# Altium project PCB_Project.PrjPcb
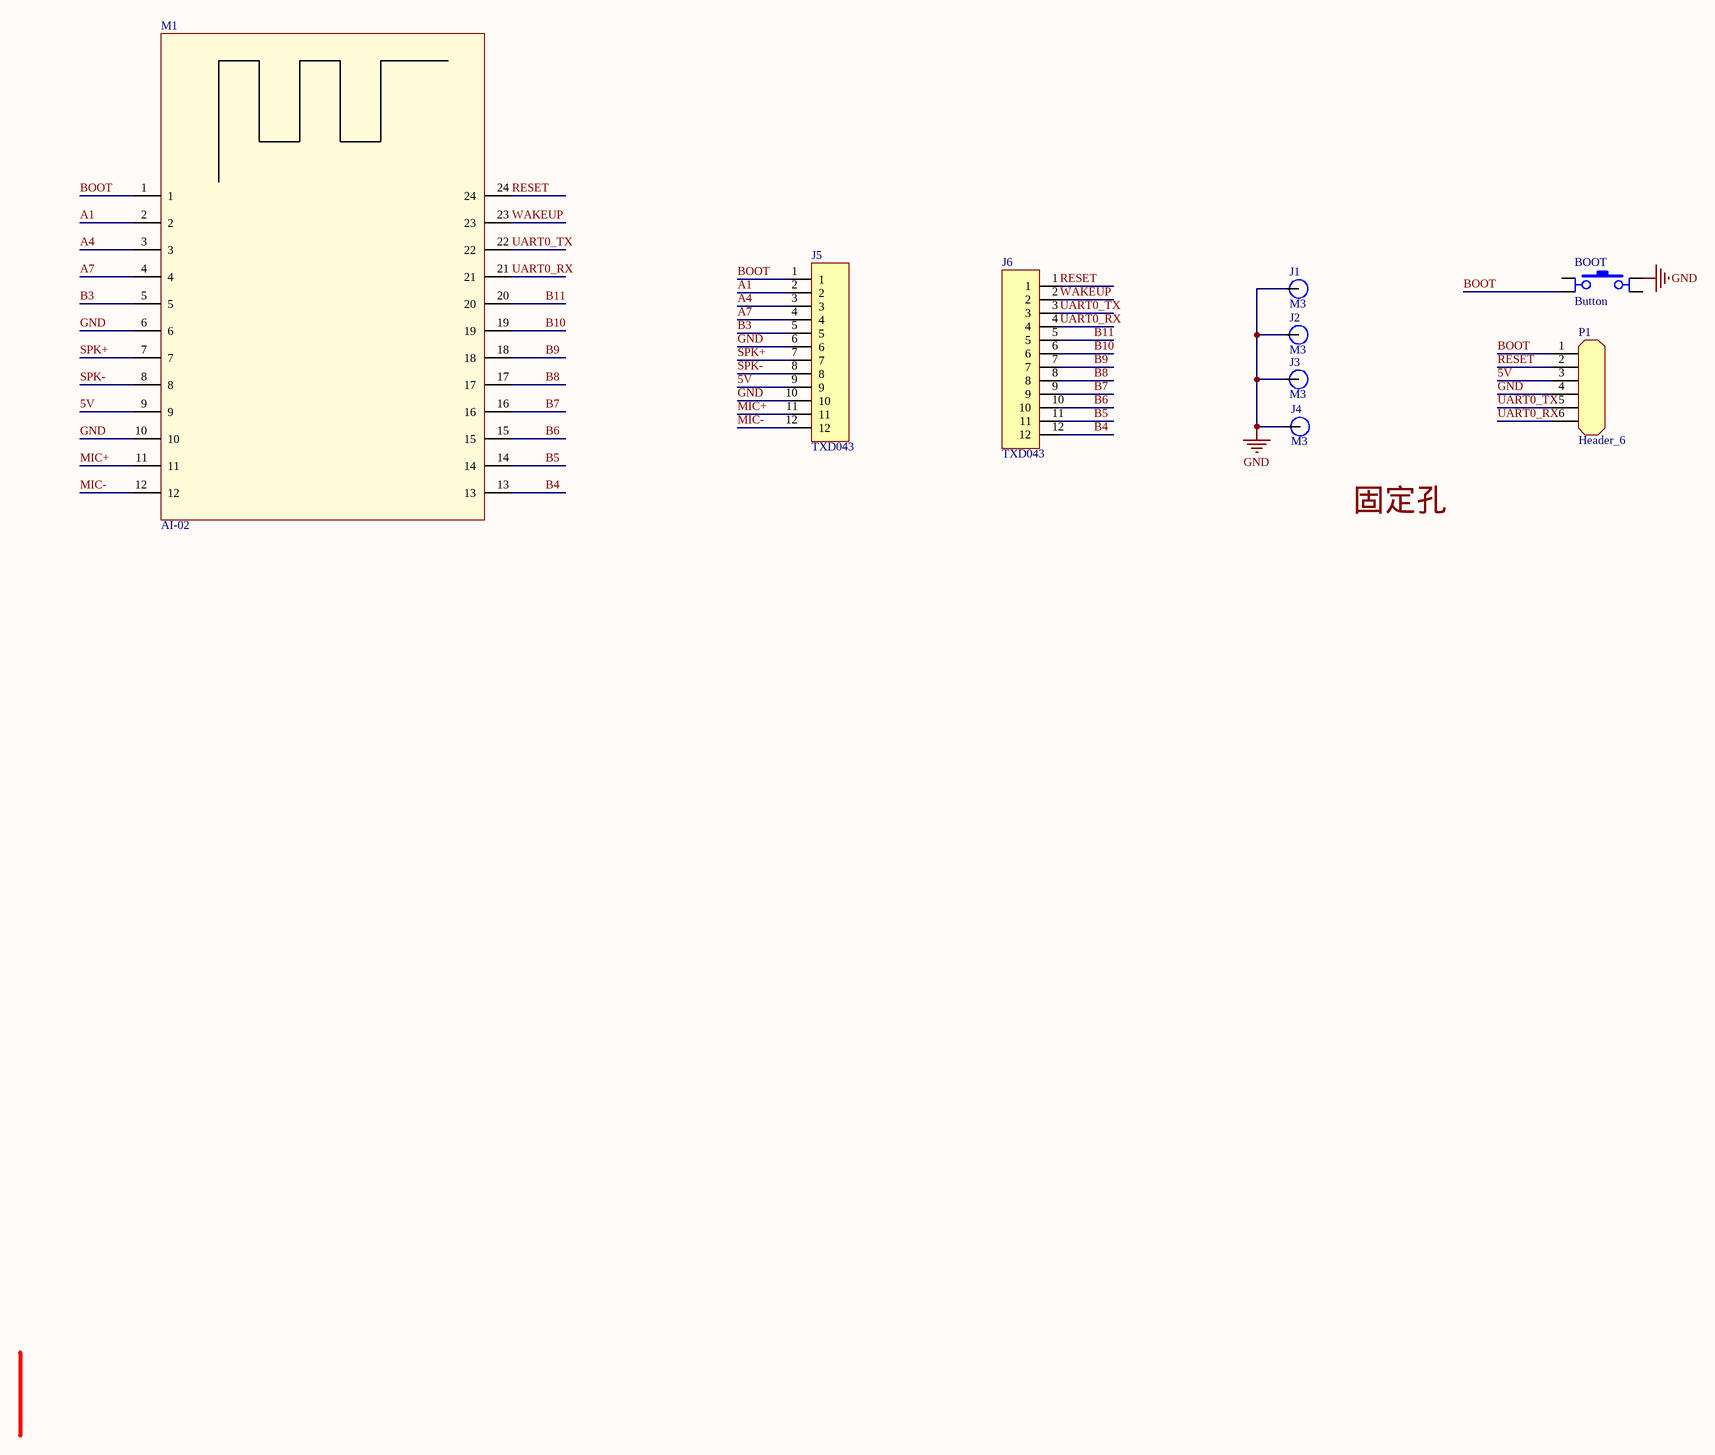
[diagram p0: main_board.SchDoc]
1 sheet, 9 parts. Net scope: global (net labels, ports and power ports of the same name join across sheets).
Board file: main_board.PcbDoc

## Sheet main_board.SchDoc
size OrCAD C

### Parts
BOOT  Button  [SW-SMD_4P-L4.2-W3.3-P2.15-LS5.1]
J1  M3  [M3 125X200]
J2  M3  [M3 125X200]
J3  M3  [M3 125X200]
J4  M3  [M3 125X200]
J5  TXD043  [PH_12PIN_DIP_2.54MM_180DEG]
J6  TXD043  [PH_12PIN_DIP_2.54MM_180DEG]
M1  AI-02  [WM-AI-Module]
P1  Header_6  [PH_6PIN_DIP_2.54MM_180DEG]

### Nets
GND: BOOT.1(PINA1) J1.1(GND) J2.1(GND) J3.1(GND) J4.1(GND) J5.6 J5.10 M1.6 M1.10 P1.4
5V: J5.9 M1.9 P1.3
A1: J5.2 M1.2
A4: J5.3 M1.3
A7: J5.4 M1.4
B3: J5.5 M1.5
B4: J6.12 M1.13
B5: J6.11 M1.14
B6: J6.10 M1.15
B7: J6.9 M1.16
B8: J6.8 M1.17
B9: J6.7 M1.18
B10: J6.6 M1.19
B11: J6.5 M1.20
BOOT: BOOT.3(PINB1) J5.1 M1.1 P1.1
MIC+: J5.11 M1.11
MIC-: J5.12 M1.12
RESET: J6.1 M1.24 P1.2
SPK+: J5.7 M1.7
SPK-: J5.8 M1.8
UART0_RX: J6.4 M1.21 P1.6
UART0_TX: J6.3 M1.22 P1.5
WAKEUP: J6.2 M1.23

Not connected (* = marked no-connect by the designer): BOOT 2(PINA2) 4(PINB2)

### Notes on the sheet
- 固定孔

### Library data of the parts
BOOT = BUTTON: Part Number: BUTTON_6x6_STAND; 02_规格参数: 按键开关-6x6-立式-直插
J1-J4 = M3: 铜柱孔; 版权归属: 源创客
J5 J6 = TXD043: 4.3寸TFT 深圳市给力光电有限公司043202B0-40-N; BOM名称: 4.3寸TFT屏
P1 = 180DIP_PH_6: 01_物料名称: 排针; 02_规格参数: 单排针 1X6P  间距2.54mm 长度11mm 直针 黑色; 03_出厂编码: 10080008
